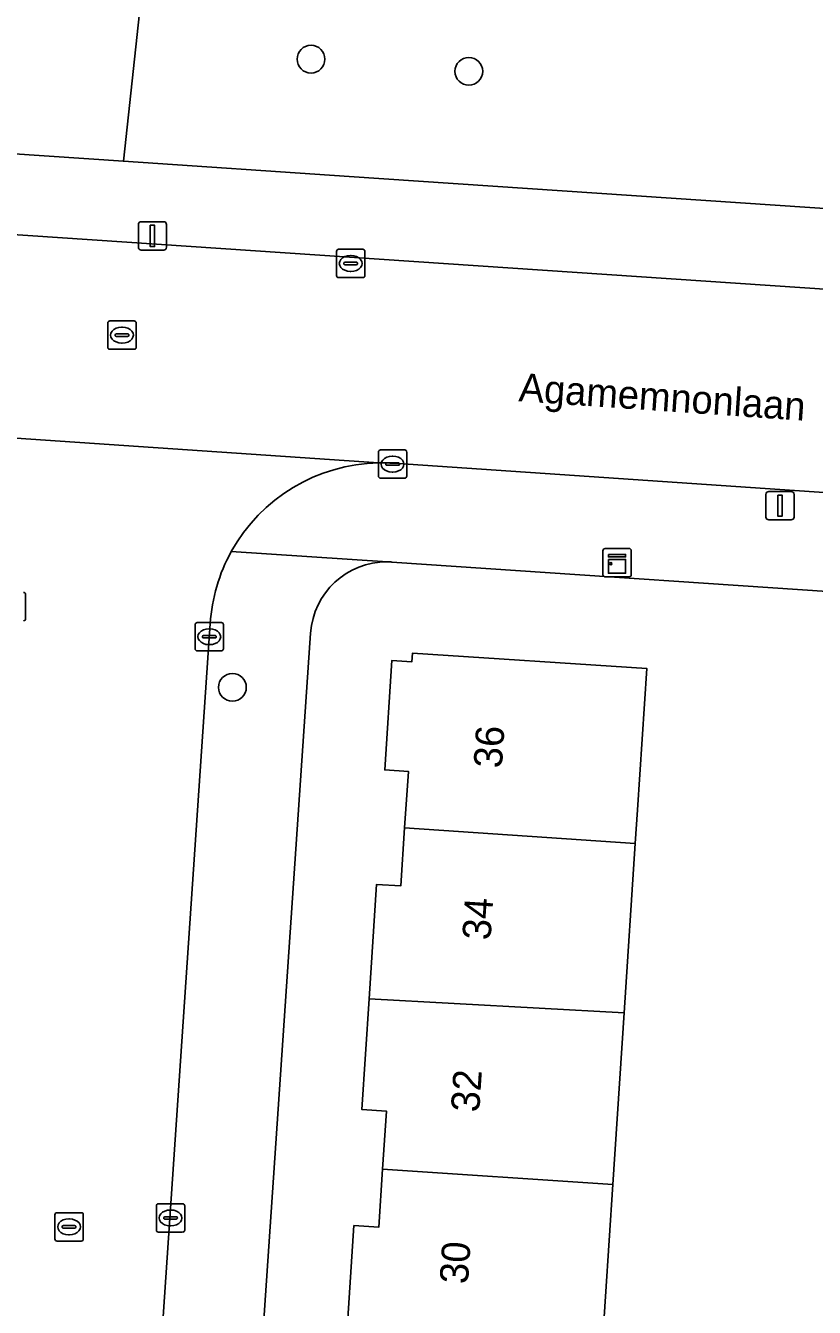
# Model space of a CAD drawing. Extents: x 161848 to 162726, y 385382 to 386521.
# Drawn here: x 162315.79 to 162343.57, y 385563.71 to 385608.89 of the extents above; entities that cross this region are included whole.
import ezdxf

# ---------------------------------------------------------------- set-up
doc = ezdxf.new("R2010")
doc.units = 0
for name, color, linetype in [('IMGEO_Boom', 7, 'Continuous'), ('IMGEO_Erf', 7, 'Continuous'), ('IMGEO_Groenvoorziening', 7, 'Continuous'), ('IMGEO_Kast', 7, 'Continuous'), ('IMGEO_Kolk', 7, 'Continuous'), ('IMGEO_Lichtmast', 7, 'Continuous'), ('IMGEO_Openbare_ruimte_label', 7, 'Continuous'), ('IMGEO_Pand', 7, 'Continuous'), ('IMGEO_Pand_nummerreeks', 7, 'Continuous'), ('IMGEO_Rijbaan_lokaal_open', 7, 'Continuous'), ('IMGEO_Rioolput', 7, 'Continuous'), ('IMGEO_Voetpad_open', 7, 'Continuous')]:
    doc.layers.add(name, color=color, linetype=linetype)

msp = doc.modelspace()

# ---------------------------------------------------------------- linework, layer by layer
at = {"layer": 'IMGEO_Boom'}
for centre in [(162325.839, 385607.704), (162331.397, 385607.276), (162323.071, 385585.565)]:
    msp.add_circle(centre, 0.489, dxfattribs=at)
at = {"layer": 'IMGEO_Erf'}
for points in [[(162344.931, 385555.437), (162345.064, 385558.071), (162348.925, 385557.878), (162349.452, 385564.997), (162345.859, 385565.234), (162346.003, 385567.417), (162346.185, 385570.171), (162349.778, 385569.934), (162350.332, 385576.757), (162346.75, 385576.995), (162346.911, 385579.421), (162347.318, 385585.552), (162347.507, 385588.704), (162328.69, 385589.98)], [(162325.823, 385587.477), (162319.885, 385500), (162317.889, 385473.417)], [(162327.089, 385562.589), (162327.351, 385566.595), (162328.226, 385566.537), (162328.36, 385568.581), (162328.494, 385570.628), (162327.63, 385570.685), (162327.886, 385574.586), (162328.15, 385578.622), (162329.002, 385578.566), (162329.136, 385580.611), (162329.267, 385582.601), (162328.437, 385582.656), (162328.69, 385586.511), (162329.395, 385586.465), (162329.416, 385586.774), (162337.664, 385586.233), (162337.337, 385581.244), (162337.26, 385580.067), (162336.868, 385574.089), (162336.472, 385568.046), (162336.083, 385562.122)]]:
    msp.add_lwpolyline(points, dxfattribs=at)
for centre, radius, start, end in [((162328.508, 385587.295), 2.691, 89.515, 176.1161), ((162328.493, 385586.878), 3.109, 86.3724, 89.3054)]:
    msp.add_arc(centre, radius, start, end, dxfattribs=at)
at = {"layer": 'IMGEO_Groenvoorziening'}
for points in [[(162313.914, 385618.371), (162310.525, 385618.197), (162307.227, 385618.391), (162299.207, 385618.52), (162290.024, 385619.62), (162287.372, 385623.112), (162282.522, 385621.172), (162278.641, 385622.853), (162272.521, 385624.409), (162263.398, 385624.644), (162261.506, 385623.382), (162259.85, 385621.49), (162259.535, 385620.15), (162259.693, 385616.365), (162261.033, 385614.788), (162265.291, 385613.054), (162271.835, 385611.556), (162272.639, 385611.354), (162274.554, 385609.13), (162276.436, 385606.992), (162319.231, 385604.108), (162319.8, 385609.337), (162317.424, 385614.541)], [(162313.914, 385618.371), (162317.424, 385614.541), (162319.8, 385609.337), (162319.231, 385604.108), (162327.188, 385603.572), (162416.342, 385597.564), (162416.584, 385600.92), (162416.956, 385606.092), (162410.55, 385606.762), (162402.009, 385607.942), (162392.382, 385608.98), (162383.322, 385610.065), (162371.949, 385611.434), (162358.453, 385613.133), (162351.893, 385613.793), (162344.437, 385614.737), (162338.68, 385615.445), (162331.554, 385616.294), (162323.249, 385617.38)]]:
    msp.add_lwpolyline(points, close=True, dxfattribs=at)
at = {"layer": 'IMGEO_Kast'}
for p, q in [((162336.121, 385589.534), (162336.121, 385590.375)), ((162336.121, 385590.375), (162336.121, 385589.534)), ((162336.196, 385590.459), (162337.037, 385590.459)), ((162337.037, 385590.459), (162336.196, 385590.459)), ((162337.121, 385590.384), (162337.121, 385589.543)), ((162337.121, 385589.543), (162337.121, 385590.384)), ((162337.046, 385589.459), (162336.205, 385589.459)), ((162336.205, 385589.459), (162337.046, 385589.459))]:
    msp.add_line(p, q, dxfattribs=at)
for points in [[(162336.316, 385590.249), (162336.916, 385590.249), (162336.916, 385590.164), (162336.316, 385590.164), (162336.316, 385590.249)], [(162336.316, 385590.074), (162336.916, 385590.074), (162336.916, 385589.585), (162336.316, 385589.585), (162336.316, 385590.074)]]:
    msp.add_lwpolyline(points, dxfattribs=at)
msp.add_circle((162336.4, 385589.923), 0.0377, dxfattribs=at)
for centre, start, end in [((162336.199, 385590.381), 92.4484, 184.2845), ((162336.199, 385590.381), 92.4484, 184.2845), ((162337.043, 385590.381), 2.4484, 94.2845), ((162337.043, 385590.381), 2.4484, 94.2845), ((162336.199, 385589.537), 182.4484, 274.2845), ((162336.199, 385589.537), 182.4484, 274.2845), ((162337.043, 385589.537), 272.4484, 4.2845), ((162337.043, 385589.537), 272.4484, 4.2845)]:
    msp.add_arc(centre, 0.0779, start, end, dxfattribs=at)
at = {"layer": 'IMGEO_Kolk'}
for p, q in [((162326.736, 385600.078), (162326.736, 385600.93)), ((162326.811, 385601.004), (162327.663, 385601.004)), ((162327.224, 385600.784), (162327.249, 385600.784)), ((162327.737, 385600.93), (162327.737, 385600.078)), ((162326.995, 385600.498), (162326.995, 385600.51)), ((162327.433, 385600.461), (162327.035, 385600.461)), ((162327.038, 385600.547), (162327.436, 385600.547)), ((162327.247, 385600.224), (162327.222, 385600.224)), ((162327.479, 385600.51), (162327.479, 385600.498)), ((162327.663, 385600.004), (162326.811, 385600.004)), ((162328.286, 385593.933), (162329.138, 385593.933)), ((162328.211, 385593.007), (162328.211, 385593.859)), ((162328.513, 385593.476), (162328.911, 385593.476)), ((162328.699, 385593.713), (162328.724, 385593.713)), ((162329.212, 385593.859), (162329.212, 385593.007)), ((162328.47, 385593.427), (162328.47, 385593.439)), ((162328.908, 385593.39), (162328.51, 385593.39)), ((162328.722, 385593.153), (162328.697, 385593.153)), ((162328.954, 385593.439), (162328.954, 385593.427)), ((162329.138, 385592.933), (162328.286, 385592.933)), ((162315.787, 385588.835), (162315.787, 385587.983)), ((162321.755, 385586.923), (162321.755, 385587.775)), ((162321.83, 385587.849), (162322.682, 385587.849)), ((162322.243, 385587.629), (162322.268, 385587.629)), ((162322.756, 385587.775), (162322.756, 385586.923)), ((162322.014, 385587.343), (162322.014, 385587.355)), ((162322.452, 385587.306), (162322.054, 385587.306)), ((162322.057, 385587.392), (162322.455, 385587.392)), ((162322.498, 385587.355), (162322.498, 385587.343)), ((162322.682, 385586.849), (162321.83, 385586.849)), ((162322.266, 385587.069), (162322.241, 385587.069)), ((162320.391, 385566.438), (162320.391, 385567.29)), ((162320.466, 385567.364), (162321.318, 385567.364)), ((162321.392, 385567.29), (162321.392, 385566.438)), ((162320.65, 385566.858), (162320.65, 385566.87)), ((162321.088, 385566.821), (162320.69, 385566.821)), ((162320.693, 385566.907), (162321.091, 385566.907)), ((162320.879, 385567.144), (162320.904, 385567.144)), ((162321.134, 385566.87), (162321.134, 385566.858)), ((162321.318, 385566.364), (162320.466, 385566.364)), ((162320.902, 385566.584), (162320.877, 385566.584))]:
    msp.add_line(p, q, dxfattribs=at)
for points in [[(162326.736, 385600.078), (162326.736, 385600.93)], [(162326.811, 385601.004), (162327.663, 385601.004)], [(162327.737, 385600.93), (162327.737, 385600.078)], [(162327.663, 385600.004), (162326.811, 385600.004)], [(162328.286, 385593.933), (162329.138, 385593.933)], [(162328.211, 385593.007), (162328.211, 385593.859)], [(162329.212, 385593.859), (162329.212, 385593.007)], [(162329.138, 385592.933), (162328.286, 385592.933)], [(162315.787, 385588.835), (162315.787, 385587.983)], [(162321.755, 385586.923), (162321.755, 385587.775)], [(162321.83, 385587.849), (162322.682, 385587.849)], [(162322.756, 385587.775), (162322.756, 385586.923)], [(162322.682, 385586.849), (162321.83, 385586.849)], [(162320.391, 385566.438), (162320.391, 385567.29)], [(162320.466, 385567.364), (162321.318, 385567.364)], [(162321.392, 385567.29), (162321.392, 385566.438)], [(162321.318, 385566.364), (162320.466, 385566.364)]]:
    msp.add_lwpolyline(points, dxfattribs=at)
for centre, radius, start, end in [((162326.813, 385600.928), 0.0765, 91.552, 178.448), ((162326.813, 385600.928), 0.0765, 91.552, 178.448), ((162327.661, 385600.928), 0.0765, 1.552, 88.448), ((162327.661, 385600.928), 0.0765, 1.552, 88.448), ((162327.035, 385600.507), 0.0403, 85.8775, 175.7526), ((162327.032, 385600.497), 0.0366, 178.938, 274.7102), ((162327.436, 385600.504), 0.043, 264.8664, 352.4533), ((162327.44, 385600.509), 0.0386, 1.7309, 96.639), ((162326.813, 385600.08), 0.0765, 181.552, 268.448), ((162326.813, 385600.08), 0.0765, 181.552, 268.448), ((162327.661, 385600.08), 0.0765, 271.552, 358.448), ((162327.661, 385600.08), 0.0765, 271.552, 358.448), ((162328.288, 385593.857), 0.0765, 91.552, 178.448), ((162328.288, 385593.857), 0.0765, 91.552, 178.448), ((162329.136, 385593.857), 0.0765, 1.552, 88.448), ((162329.136, 385593.857), 0.0765, 1.552, 88.448), ((162328.51, 385593.436), 0.0403, 85.8775, 175.7526), ((162328.915, 385593.438), 0.0386, 1.7309, 96.639), ((162328.288, 385593.009), 0.0765, 181.552, 268.448), ((162328.288, 385593.009), 0.0765, 181.552, 268.448), ((162328.507, 385593.426), 0.0366, 178.938, 274.7102), ((162328.911, 385593.433), 0.043, 264.8664, 352.4533), ((162329.136, 385593.009), 0.0765, 271.552, 358.448), ((162329.136, 385593.009), 0.0765, 271.552, 358.448), ((162315.711, 385588.833), 0.0765, 1.552, 88.448), ((162315.711, 385588.833), 0.0765, 1.552, 88.448), ((162315.711, 385587.985), 0.0765, 271.552, 358.448), ((162315.711, 385587.985), 0.0765, 271.552, 358.448), ((162321.832, 385587.773), 0.0765, 91.552, 178.448), ((162321.832, 385587.773), 0.0765, 91.552, 178.448), ((162322.68, 385587.773), 0.0765, 1.552, 88.448), ((162322.68, 385587.773), 0.0765, 1.552, 88.448), ((162322.054, 385587.352), 0.0403, 85.8775, 175.7526), ((162322.051, 385587.342), 0.0366, 178.938, 274.7102), ((162322.455, 385587.349), 0.043, 264.8664, 352.4533), ((162322.459, 385587.354), 0.0386, 1.7309, 96.639), ((162321.832, 385586.925), 0.0765, 181.552, 268.448), ((162321.832, 385586.925), 0.0765, 181.552, 268.448), ((162322.68, 385586.925), 0.0765, 271.552, 358.448), ((162322.68, 385586.925), 0.0765, 271.552, 358.448), ((162320.468, 385567.288), 0.0765, 91.552, 178.448), ((162320.468, 385567.288), 0.0765, 91.552, 178.448), ((162321.316, 385567.288), 0.0765, 1.552, 88.448), ((162321.316, 385567.288), 0.0765, 1.552, 88.448), ((162320.69, 385566.867), 0.0403, 85.8775, 175.7526), ((162320.687, 385566.857), 0.0366, 178.938, 274.7102), ((162321.091, 385566.864), 0.043, 264.8664, 352.4533), ((162321.095, 385566.869), 0.0386, 1.7309, 96.639), ((162320.468, 385566.44), 0.0765, 181.552, 268.448), ((162320.468, 385566.44), 0.0765, 181.552, 268.448), ((162321.316, 385566.44), 0.0765, 271.552, 358.448), ((162321.316, 385566.44), 0.0765, 271.552, 358.448)]:
    msp.add_arc(centre, radius, start, end, dxfattribs=at)
for centre, major_axis, ratio, start_param, end_param in [((162327.223, 385600.504), (-0.387, 0.002), 0.722429, 4.712389, 7.853982), ((162327.248, 385600.504), (-0.39, 0.002), 0.717154, 1.570796, 4.712389), ((162328.698, 385593.433), (-0.387, 0.002), 0.722429, 4.712389, 7.853982), ((162328.723, 385593.433), (-0.39, 0.002), 0.717154, 1.570796, 4.712389), ((162322.242, 385587.349), (-0.387, 0.002), 0.722429, 4.712389, 7.853982), ((162322.267, 385587.349), (-0.39, 0.002), 0.717154, 1.570796, 4.712389), ((162320.878, 385566.864), (-0.387, 0.002), 0.722429, 4.712389, 7.853982), ((162320.903, 385566.864), (-0.39, 0.002), 0.717154, 1.570796, 4.712389)]:
    msp.add_ellipse(centre, major_axis=major_axis, ratio=ratio, start_param=start_param, end_param=end_param, dxfattribs=at)
at = {"layer": 'IMGEO_Lichtmast'}
for p, q in [((162319.759, 385601.075), (162319.759, 385601.875)), ((162319.759, 385601.875), (162319.759, 385601.075)), ((162319.859, 385601.975), (162320.649, 385601.975)), ((162320.649, 385601.975), (162319.859, 385601.975)), ((162320.749, 385601.875), (162320.749, 385601.075)), ((162320.749, 385601.075), (162320.749, 385601.875)), ((162320.649, 385600.975), (162319.859, 385600.975)), ((162319.859, 385600.975), (162320.649, 385600.975)), ((162341.863, 385591.567), (162341.863, 385592.367)), ((162341.863, 385592.367), (162341.863, 385591.567)), ((162341.963, 385592.467), (162342.753, 385592.467)), ((162342.753, 385592.467), (162341.963, 385592.467)), ((162342.853, 385592.367), (162342.853, 385591.567)), ((162342.853, 385591.567), (162342.853, 385592.367)), ((162342.753, 385591.467), (162341.963, 385591.467)), ((162341.963, 385591.467), (162342.753, 385591.467))]:
    msp.add_line(p, q, dxfattribs=at)
for points in [[(162320.179, 385601.85), (162320.329, 385601.85), (162320.329, 385601.1), (162320.179, 385601.1), (162320.179, 385601.85)], [(162342.283, 385592.342), (162342.433, 385592.342), (162342.433, 385591.592), (162342.283, 385591.592), (162342.283, 385592.342)]]:
    msp.add_lwpolyline(points, dxfattribs=at)
for centre, start, end in [((162319.859, 385601.875), 90, 180), ((162319.859, 385601.875), 90, 180), ((162320.649, 385601.875), 0, 90), ((162320.649, 385601.875), 360, 90), ((162319.859, 385601.075), 180, 270), ((162319.859, 385601.075), 180, 270), ((162320.649, 385601.075), 270, 0), ((162320.649, 385601.075), 270, 0), ((162341.963, 385592.367), 90, 180), ((162341.963, 385592.367), 90, 180), ((162342.753, 385592.367), 0, 90), ((162342.753, 385592.367), 360, 90), ((162341.963, 385591.567), 180, 270), ((162341.963, 385591.567), 180, 270), ((162342.753, 385591.567), 270, 0), ((162342.753, 385591.567), 270, 0)]:
    msp.add_arc(centre, 0.1, start, end, dxfattribs=at)
at = {"layer": 'IMGEO_Pand'}
for points in [[(162337.26, 385580.067), (162337.337, 385581.244), (162337.664, 385586.233), (162329.416, 385586.774), (162329.395, 385586.465), (162328.69, 385586.511), (162328.437, 385582.656), (162329.267, 385582.601), (162329.136, 385580.611)], [(162329.136, 385580.611), (162329.002, 385578.566), (162328.15, 385578.622), (162327.886, 385574.586), (162336.868, 385574.089), (162337.26, 385580.067)], [(162327.886, 385574.586), (162327.63, 385570.685), (162328.494, 385570.628), (162328.36, 385568.581), (162336.472, 385568.046), (162336.868, 385574.089)], [(162336.083, 385562.122), (162336.472, 385568.046), (162328.36, 385568.581), (162328.226, 385566.537), (162327.351, 385566.595), (162327.089, 385562.589)]]:
    msp.add_lwpolyline(points, close=True, dxfattribs=at)
at = {"layer": 'IMGEO_Rijbaan_lokaal_open'}
for points in [[(162250.141, 385605.918), (162241.588, 385606.517), (162240.952, 385599.422), (162246.169, 385599.107), (162309.752, 385594.736), (162328.221, 385593.475)], [(162392.515, 385589.122), (162412.585, 385587.758), (162415.011, 385587.593), (162431.505, 385586.582), (162435.655, 385586.297), (162436.128, 385593.403), (162432.653, 385593.623), (162250.141, 385605.918)], [(162328.221, 385593.475), (162309.752, 385594.736)], [(162328.746, 385593.462), (162347.698, 385592.175), (162351.299, 385591.93), (162352.879, 385591.823), (162356.465, 385591.579), (162373.555, 385590.418), (162391.947, 385589.134)], [(162319.604, 385548.271), (162319.865, 385552.12), (162322.286, 385587.816)]]:
    msp.add_lwpolyline(points, dxfattribs=at)
for centre, radius, start, end in [((162328.337, 385587.411), 6.065, 91.0957, 151.0264), ((162328.328, 385587.189), 6.287, 86.1878, 90.9753), ((162328.344, 385587.41), 6.071, 151.0521, 176.1688)]:
    msp.add_arc(centre, radius, start, end, dxfattribs=at)
at = {"layer": 'IMGEO_Rioolput'}
for p, q in [((162318.755, 385598.478), (162319.607, 385598.478)), ((162318.68, 385597.552), (162318.68, 385598.404)), ((162318.939, 385597.972), (162318.939, 385597.984)), ((162318.982, 385598.021), (162319.38, 385598.021)), ((162319.168, 385598.258), (162319.193, 385598.258)), ((162319.423, 385597.984), (162319.423, 385597.972)), ((162319.681, 385598.404), (162319.681, 385597.552)), ((162319.377, 385597.935), (162318.979, 385597.935)), ((162319.191, 385597.698), (162319.166, 385597.698)), ((162319.607, 385597.478), (162318.755, 385597.478)), ((162316.817, 385566.124), (162316.817, 385566.976)), ((162316.892, 385567.05), (162317.744, 385567.05)), ((162317.305, 385566.83), (162317.33, 385566.83)), ((162317.818, 385566.976), (162317.818, 385566.124)), ((162317.076, 385566.544), (162317.076, 385566.556)), ((162317.514, 385566.507), (162317.116, 385566.507)), ((162317.119, 385566.593), (162317.517, 385566.593)), ((162317.56, 385566.556), (162317.56, 385566.544)), ((162317.744, 385566.05), (162316.892, 385566.05)), ((162317.328, 385566.27), (162317.303, 385566.27))]:
    msp.add_line(p, q, dxfattribs=at)
for points in [[(162318.755, 385598.478), (162319.607, 385598.478)], [(162318.68, 385597.552), (162318.68, 385598.404)], [(162319.681, 385598.404), (162319.681, 385597.552)], [(162319.607, 385597.478), (162318.755, 385597.478)], [(162316.817, 385566.124), (162316.817, 385566.976)], [(162316.892, 385567.05), (162317.744, 385567.05)], [(162317.818, 385566.976), (162317.818, 385566.124)], [(162317.744, 385566.05), (162316.892, 385566.05)]]:
    msp.add_lwpolyline(points, dxfattribs=at)
for centre, radius, start, end in [((162318.757, 385598.402), 0.0765, 91.552, 178.448), ((162318.757, 385598.402), 0.0765, 91.552, 178.448), ((162319.605, 385598.402), 0.0765, 1.552, 88.448), ((162319.605, 385598.402), 0.0765, 1.552, 88.448), ((162318.979, 385597.981), 0.0403, 85.8775, 175.7526), ((162318.976, 385597.971), 0.0366, 178.938, 274.7102), ((162319.38, 385597.978), 0.043, 264.8664, 352.4533), ((162319.384, 385597.983), 0.0386, 1.7309, 96.639), ((162318.757, 385597.554), 0.0765, 181.552, 268.448), ((162318.757, 385597.554), 0.0765, 181.552, 268.448), ((162319.605, 385597.554), 0.0765, 271.552, 358.448), ((162319.605, 385597.554), 0.0765, 271.552, 358.448), ((162316.894, 385566.974), 0.0765, 91.552, 178.448), ((162316.894, 385566.974), 0.0765, 91.552, 178.448), ((162317.742, 385566.974), 0.0765, 1.552, 88.448), ((162317.742, 385566.974), 0.0765, 1.552, 88.448), ((162317.116, 385566.553), 0.0403, 85.8775, 175.7526), ((162317.113, 385566.543), 0.0366, 178.938, 274.7102), ((162317.517, 385566.55), 0.043, 264.8664, 352.4533), ((162317.521, 385566.555), 0.0386, 1.7309, 96.639), ((162316.894, 385566.126), 0.0765, 181.552, 268.448), ((162316.894, 385566.126), 0.0765, 181.552, 268.448), ((162317.742, 385566.126), 0.0765, 271.552, 358.448), ((162317.742, 385566.126), 0.0765, 271.552, 358.448)]:
    msp.add_arc(centre, radius, start, end, dxfattribs=at)
for centre, major_axis, ratio, start_param, end_param in [((162319.167, 385597.978), (-0.387, 0.002), 0.722429, 4.712389, 7.853982), ((162319.192, 385597.978), (-0.39, 0.002), 0.717154, 1.570796, 4.712389), ((162317.304, 385566.55), (-0.387, 0.002), 0.722429, 4.712389, 7.853982), ((162317.329, 385566.55), (-0.39, 0.002), 0.717154, 1.570796, 4.712389)]:
    msp.add_ellipse(centre, major_axis=major_axis, ratio=ratio, start_param=start_param, end_param=end_param, dxfattribs=at)
at = {"layer": 'IMGEO_Voetpad_open'}
for points in [[(162416.342, 385597.564), (162327.188, 385603.572), (162319.231, 385604.108), (162276.436, 385606.992), (162272.52, 385607.256), (162238.603, 385609.542), (162225.673, 385610.463), (162225.228, 385604.48), (162224.178, 385588.393)], [(162234.379, 385607.022), (162241.588, 385606.517), (162250.141, 385605.918), (162432.653, 385593.623), (162436.128, 385593.403), (162437.247, 385593.361)], [(162373.555, 385590.418), (162356.465, 385591.579), (162352.879, 385591.823), (162351.299, 385591.93), (162347.698, 385592.175), (162328.746, 385593.462)], [(162328.531, 385589.986), (162323.031, 385590.349)], [(162323.031, 385590.349), (162328.531, 385589.986)], [(162328.69, 385589.98), (162347.507, 385588.704), (162352.664, 385588.358), (162362.885, 385587.655), (162371.066, 385587.092), (162372.682, 385586.981), (162374.863, 385586.831), (162377.857, 385587.803)], [(162322.286, 385587.816), (162319.865, 385552.12), (162319.604, 385548.271), (162316.33, 385500), (162314.478, 385474.919)], [(162317.889, 385473.417), (162319.885, 385500), (162325.823, 385587.477)]]:
    msp.add_lwpolyline(points, dxfattribs=at)
for centre, radius, start, end in [((162328.337, 385587.411), 6.065, 91.0957, 151.0264), ((162328.328, 385587.189), 6.287, 86.1878, 90.9753), ((162328.344, 385587.41), 6.071, 151.0521, 176.1688), ((162328.508, 385587.295), 2.691, 89.515, 176.1161), ((162328.493, 385586.878), 3.109, 86.3724, 89.3054)]:
    msp.add_arc(centre, radius, start, end, dxfattribs=at)

# ---------------------------------------------------------------- texts
at = {"layer": 'IMGEO_Openbare_ruimte_label'}
msp.add_text('Agamemnonlaan', height=1, rotation=356.1021, dxfattribs=at).set_placement((162333.134, 385595.648))
at = {"layer": 'IMGEO_Pand_nummerreeks'}
for s, p in [('36', (162332.559, 385582.696)), ('34', (162332.161, 385576.636)), ('32', (162331.762, 385570.572)), ('30', (162331.365, 385564.517))]:
    msp.add_text(s, height=1, rotation=86.2375, dxfattribs=at).set_placement(p)

doc.saveas('drawing.dxf')
